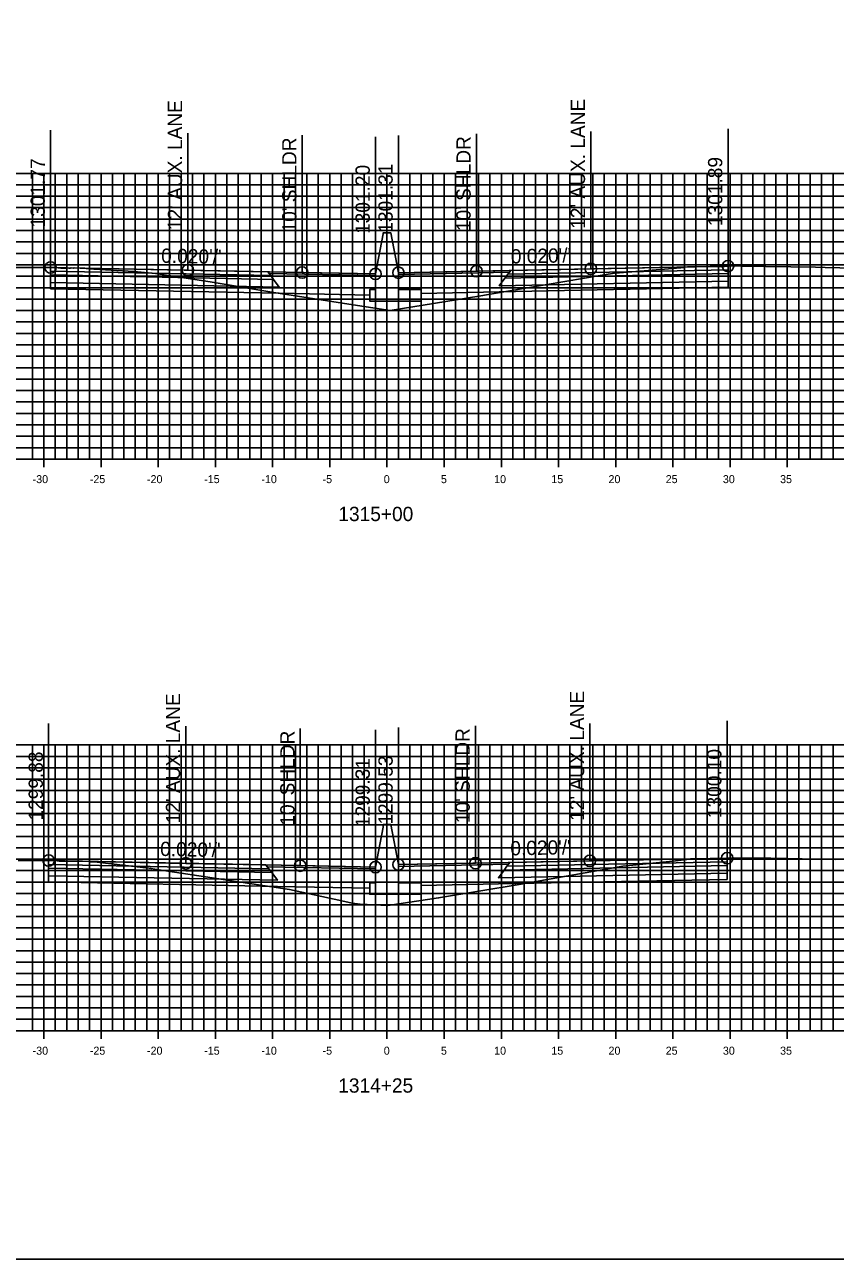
# Model space of a CAD drawing. Extents: x 674939 to 678919, y 750652 to 765176.
# Drawn here: x 678706.9 to 678777.7, y 750922.6 to 751030.6 of the extents above; entities that cross this region are included whole.
import ezdxf

# ---------------------------------------------------------------- set-up
doc = ezdxf.new("R2010")
doc.units = 0
for name, color, linetype in [('R_Alt Surface', 7, 'Continuous'), ('R_Axis', 7, 'Continuous'), ('R_Axis Annot', 7, 'Continuous'), ('R_Exist Surface', 7, 'Continuous'), ('R_Fin Surface', 7, 'Continuous'), ('R_Grid', 7, 'Continuous'), ('R_No Plot', 7, 'Continuous'), ('R_Proposed Road', 7, 'Continuous'), ('R_Xsect Elev', 7, 'Continuous'), ('R_Xsect Slope', 7, 'Continuous')]:
    doc.layers.add(name, color=color, linetype=linetype)

msp = doc.modelspace()

# ---------------------------------------------------------------- linework, layer by layer
at = {"layer": 'R_Alt Surface'}
for points in [[(678709.12, 751008.99), (678709.12, 751008.66), (678728.62, 751008.27), (678728.37, 751008.61)], [(678709.12, 751008.66), (678709.12, 751008), (678729.12, 751007.6), (678728.62, 751008.27)], [(678768.35, 751008.78), (678768.35, 751008.12), (678748.35, 751007.72), (678748.85, 751008.39)], [(678768.35, 751009.11), (678768.35, 751008.78), (678748.85, 751008.39), (678749.1, 751008.72)], [(678708.95, 750957.1), (678708.95, 750956.77), (678728.45, 750956.38), (678728.2, 750956.72)], [(678768.27, 750956.99), (678768.27, 750956.33), (678748.27, 750955.93), (678748.77, 750956.6)], [(678768.27, 750957.32), (678768.27, 750956.99), (678748.77, 750956.6), (678749.02, 750956.94)], [(678708.95, 750956.77), (678708.95, 750956.11), (678728.95, 750955.71), (678728.45, 750956.38)]]:
    msp.add_lwpolyline(points, close=True, dxfattribs=at)
for points in [[(678709.12, 751008), (678709.12, 751007.46), (678729.12, 751007.06), (678737.03, 751006.9)], [(678768.35, 751008.12), (678768.35, 751007.58), (678748.35, 751007.18), (678741.53, 751007.04)], [(678708.95, 750956.11), (678708.95, 750955.57), (678728.95, 750955.17), (678737.03, 750955.01)], [(678768.27, 750956.33), (678768.27, 750955.79), (678748.27, 750955.39), (678741.53, 750955.26)]]:
    msp.add_lwpolyline(points, dxfattribs=at)
at = {"layer": 'R_Axis'}
for p, q in [((678638.53, 750992.55), (678838.53, 750992.55)), ((678708.53, 750991.85), (678708.53, 750993.25)), ((678713.53, 750991.85), (678713.53, 750993.25)), ((678718.53, 750991.85), (678718.53, 750993.25)), ((678723.53, 750991.85), (678723.53, 750993.25)), ((678728.53, 750991.85), (678728.53, 750993.25)), ((678733.53, 750991.85), (678733.53, 750993.25)), ((678738.53, 750991.85), (678738.53, 750993.25)), ((678743.53, 750991.85), (678743.53, 750993.25)), ((678748.53, 750991.85), (678748.53, 750993.25)), ((678753.53, 750991.85), (678753.53, 750993.25)), ((678758.53, 750991.85), (678758.53, 750993.25)), ((678763.53, 750991.85), (678763.53, 750993.25)), ((678768.53, 750991.85), (678768.53, 750993.25)), ((678773.53, 750991.85), (678773.53, 750993.25)), ((678708.53, 750941.85), (678708.53, 750943.25)), ((678713.53, 750941.85), (678713.53, 750943.25)), ((678718.53, 750941.85), (678718.53, 750943.25)), ((678723.53, 750941.85), (678723.53, 750943.25)), ((678728.53, 750941.85), (678728.53, 750943.25)), ((678733.53, 750941.85), (678733.53, 750943.25)), ((678738.53, 750941.85), (678738.53, 750943.25)), ((678743.53, 750941.85), (678743.53, 750943.25)), ((678748.53, 750941.85), (678748.53, 750943.25)), ((678753.53, 750941.85), (678753.53, 750943.25)), ((678758.53, 750941.85), (678758.53, 750943.25)), ((678763.53, 750941.85), (678763.53, 750943.25)), ((678768.53, 750941.85), (678768.53, 750943.25)), ((678773.53, 750941.85), (678773.53, 750943.25)), ((678638.53, 750942.55), (678838.53, 750942.55))]:
    msp.add_line(p, q, dxfattribs=at)
at = {"layer": 'R_Exist Surface'}
for points in [[(678705.21, 751009.31), (678707.58, 751009.31), (678709.09, 751009.32), (678709.12, 751009.32), (678709.18, 751009.32), (678709.53, 751009.3), (678710.01, 751009.27), (678710.47, 751009.27), (678710.55, 751009.28), (678710.72, 751009.26), (678710.84, 751009.27), (678710.92, 751009.28), (678711.09, 751009.27), (678711.17, 751009.28), (678712.22, 751009.23), (678712.47, 751009.21), (678712.64, 751009.2), (678712.75, 751009.21), (678712.87, 751009.19), (678712.93, 751009.18), (678716.41, 751008.95), (678718.29, 751008.79), (678723.07, 751008.05), (678728.65, 751007.14), (678736.34, 751005.94), (678738.82, 751005.55), (678746.55, 751006.81), (678748.93, 751007.22), (678757.52, 751008.66), (678758.43, 751008.81), (678758.69, 751008.85), (678758.87, 751008.86), (678764.57, 751009.32), (678764.61, 751009.33), (678764.82, 751009.37), (678765.08, 751009.38), (678766.79, 751009.41), (678766.99, 751009.41), (678768.02, 751009.41), (678768.07, 751009.42), (678768.35, 751009.44), (678768.37, 751009.44), (678768.59, 751009.46), (678769.49, 751009.44), (678775.99, 751009.34), (678776.83, 751009.32), (678785.72, 751009.1)], [(678706.28, 750957.43), (678708.11, 750957.43), (678708.95, 750957.43), (678708.97, 750957.43), (678709.23, 750957.43), (678709.69, 750957.41), (678709.86, 750957.39), (678710.36, 750957.39), (678711.41, 750957.39), (678711.91, 750957.39), (678712.49, 750957.34), (678712.57, 750957.32), (678712.78, 750957.32), (678712.93, 750957.33), (678717.46, 750956.79), (678717.75, 750956.76), (678718.42, 750956.65), (678730, 750954.91), (678734.58, 750953.92), (678735.5, 750953.7), (678736.19, 750953.63), (678738.61, 750953.49), (678743.05, 750954.17), (678750.08, 750955.35), (678753.89, 750956.02), (678759.14, 750956.94), (678763.51, 750957.39), (678764.72, 750957.52), (678764.72, 750957.52), (678764.75, 750957.53), (678765.06, 750957.57), (678765.32, 750957.59), (678767.21, 750957.62), (678767.38, 750957.61), (678768.06, 750957.61), (678768.12, 750957.62), (678768.27, 750957.65), (678768.29, 750957.66), (678768.29, 750957.66), (678771.2, 750957.64), (678772.1, 750957.63), (678776.2, 750957.55), (678777.77, 750957.52)]]:
    msp.add_lwpolyline(points, dxfattribs=at)
at = {"layer": 'R_Fin Surface'}
for points in [[(678737.53, 751008.75), (678731.12, 751008.88), (678721.12, 751009.08), (678709.12, 751009.32)], [(678768.35, 751009.44), (678756.35, 751009.2), (678746.35, 751009), (678739.53, 751008.86)], [(678737.53, 750956.86), (678730.95, 750956.99), (678720.95, 750957.19), (678708.95, 750957.43)], [(678768.27, 750957.65), (678756.27, 750957.41), (678746.27, 750957.21), (678739.53, 750957.08)]]:
    msp.add_lwpolyline(points, dxfattribs=at)
for points in [[(678709.12, 751009.32), (678709.12, 751008.99), (678728.37, 751008.61), (678728.12, 751008.94)], [(678728.12, 751008.94), (678737.53, 751008.75), (678737.54, 751008.6), (678728.24, 751008.78)], [(678749.24, 751008.9), (678739.53, 751008.71), (678739.53, 751008.86), (678749.35, 751009.06)], [(678768.35, 751009.44), (678768.35, 751009.11), (678749.1, 751008.72), (678749.35, 751009.06)], [(678708.95, 750957.43), (678708.95, 750957.1), (678728.2, 750956.72), (678727.95, 750957.05)], [(678727.95, 750957.05), (678737.53, 750956.86), (678737.54, 750956.7), (678728.07, 750956.89)], [(678749.15, 750957.12), (678739.53, 750956.92), (678739.53, 750957.08), (678749.27, 750957.27)], [(678768.27, 750957.65), (678768.27, 750957.32), (678749.02, 750956.94), (678749.27, 750957.27)]]:
    msp.add_lwpolyline(points, close=True, dxfattribs=at)
at = {"layer": 'R_Grid'}
for p, q in [((678638.53, 751017.55), (678838.53, 751017.55)), ((678707.53, 750992.55), (678707.53, 751017.55)), ((678708.53, 750992.55), (678708.53, 751017.55)), ((678709.53, 750992.55), (678709.53, 751017.55)), ((678710.53, 750992.55), (678710.53, 751017.55)), ((678711.53, 750992.55), (678711.53, 751017.55)), ((678712.53, 750992.55), (678712.53, 751017.55)), ((678713.53, 750992.55), (678713.53, 751017.55)), ((678714.53, 750992.55), (678714.53, 751017.55)), ((678715.53, 750992.55), (678715.53, 751017.55)), ((678716.53, 750992.55), (678716.53, 751017.55)), ((678717.53, 750992.55), (678717.53, 751017.55)), ((678718.53, 750992.55), (678718.53, 751017.55)), ((678719.53, 750992.55), (678719.53, 751017.55)), ((678720.53, 750992.55), (678720.53, 751017.55)), ((678721.53, 750992.55), (678721.53, 751017.55)), ((678722.53, 750992.55), (678722.53, 751017.55)), ((678723.53, 750992.55), (678723.53, 751017.55)), ((678724.53, 750992.55), (678724.53, 751017.55)), ((678725.53, 750992.55), (678725.53, 751017.55)), ((678726.53, 750992.55), (678726.53, 751017.55)), ((678727.53, 750992.55), (678727.53, 751017.55)), ((678728.53, 750992.55), (678728.53, 751017.55)), ((678729.53, 750992.55), (678729.53, 751017.55)), ((678730.53, 750992.55), (678730.53, 751017.55)), ((678731.53, 750992.55), (678731.53, 751017.55)), ((678732.53, 750992.55), (678732.53, 751017.55)), ((678733.53, 750992.55), (678733.53, 751017.55)), ((678734.53, 750992.55), (678734.53, 751017.55)), ((678735.53, 750992.55), (678735.53, 751017.55)), ((678736.53, 750992.55), (678736.53, 751017.55)), ((678737.53, 750992.55), (678737.53, 751017.55)), ((678738.53, 750992.55), (678738.53, 751017.55)), ((678739.53, 750992.55), (678739.53, 751017.55)), ((678740.53, 750992.55), (678740.53, 751017.55)), ((678741.53, 750992.55), (678741.53, 751017.55)), ((678742.53, 750992.55), (678742.53, 751017.55)), ((678743.53, 750992.55), (678743.53, 751017.55)), ((678744.53, 750992.55), (678744.53, 751017.55)), ((678745.53, 750992.55), (678745.53, 751017.55)), ((678746.53, 750992.55), (678746.53, 751017.55)), ((678747.53, 750992.55), (678747.53, 751017.55)), ((678748.53, 750992.55), (678748.53, 751017.55)), ((678749.53, 750992.55), (678749.53, 751017.55)), ((678750.53, 750992.55), (678750.53, 751017.55)), ((678751.53, 750992.55), (678751.53, 751017.55)), ((678752.53, 750992.55), (678752.53, 751017.55)), ((678753.53, 750992.55), (678753.53, 751017.55)), ((678754.53, 750992.55), (678754.53, 751017.55)), ((678755.53, 750992.55), (678755.53, 751017.55)), ((678756.53, 750992.55), (678756.53, 751017.55)), ((678757.53, 750992.55), (678757.53, 751017.55)), ((678758.53, 750992.55), (678758.53, 751017.55)), ((678759.53, 750992.55), (678759.53, 751017.55)), ((678760.53, 750992.55), (678760.53, 751017.55)), ((678761.53, 750992.55), (678761.53, 751017.55)), ((678762.53, 750992.55), (678762.53, 751017.55)), ((678763.53, 750992.55), (678763.53, 751017.55)), ((678764.53, 750992.55), (678764.53, 751017.55)), ((678765.53, 750992.55), (678765.53, 751017.55)), ((678766.53, 750992.55), (678766.53, 751017.55)), ((678767.53, 750992.55), (678767.53, 751017.55)), ((678768.53, 750992.55), (678768.53, 751017.55)), ((678769.53, 750992.55), (678769.53, 751017.55)), ((678770.53, 750992.55), (678770.53, 751017.55)), ((678771.53, 750992.55), (678771.53, 751017.55)), ((678772.53, 750992.55), (678772.53, 751017.55)), ((678773.53, 750992.55), (678773.53, 751017.55)), ((678774.53, 750992.55), (678774.53, 751017.55)), ((678775.53, 750992.55), (678775.53, 751017.55)), ((678776.53, 750992.55), (678776.53, 751017.55)), ((678777.53, 750992.55), (678777.53, 751017.55)), ((678638.53, 751016.55), (678838.53, 751016.55)), ((678638.53, 751015.55), (678838.53, 751015.55)), ((678638.53, 751014.55), (678838.53, 751014.55)), ((678638.53, 751013.55), (678838.53, 751013.55)), ((678638.53, 751012.55), (678838.53, 751012.55)), ((678638.53, 751011.55), (678838.53, 751011.55)), ((678638.53, 751010.55), (678838.53, 751010.55)), ((678638.53, 751009.55), (678838.53, 751009.55)), ((678638.53, 751008.55), (678838.53, 751008.55)), ((678638.53, 751007.55), (678838.53, 751007.55)), ((678638.53, 751006.55), (678838.53, 751006.55)), ((678638.53, 751005.55), (678838.53, 751005.55)), ((678638.53, 751004.55), (678838.53, 751004.55)), ((678638.53, 751003.55), (678838.53, 751003.55)), ((678638.53, 751002.55), (678838.53, 751002.55)), ((678638.53, 751001.55), (678838.53, 751001.55)), ((678638.53, 751000.55), (678838.53, 751000.55)), ((678638.53, 750999.55), (678838.53, 750999.55)), ((678638.53, 750998.55), (678838.53, 750998.55)), ((678638.53, 750997.55), (678838.53, 750997.55)), ((678638.53, 750996.55), (678838.53, 750996.55)), ((678638.53, 750995.55), (678838.53, 750995.55)), ((678638.53, 750994.55), (678838.53, 750994.55)), ((678638.53, 750993.55), (678838.53, 750993.55)), ((678638.53, 750992.55), (678838.53, 750992.55)), ((678638.53, 750967.55), (678838.53, 750967.55)), ((678638.53, 750966.55), (678838.53, 750966.55)), ((678707.53, 750942.55), (678707.53, 750967.55)), ((678708.53, 750942.55), (678708.53, 750967.55)), ((678709.53, 750942.55), (678709.53, 750967.55)), ((678710.53, 750942.55), (678710.53, 750967.55)), ((678711.53, 750942.55), (678711.53, 750967.55)), ((678712.53, 750942.55), (678712.53, 750967.55)), ((678713.53, 750942.55), (678713.53, 750967.55)), ((678714.53, 750942.55), (678714.53, 750967.55)), ((678715.53, 750942.55), (678715.53, 750967.55)), ((678716.53, 750942.55), (678716.53, 750967.55)), ((678717.53, 750942.55), (678717.53, 750967.55)), ((678718.53, 750942.55), (678718.53, 750967.55)), ((678719.53, 750942.55), (678719.53, 750967.55)), ((678720.53, 750942.55), (678720.53, 750967.55)), ((678721.53, 750942.55), (678721.53, 750967.55)), ((678722.53, 750942.55), (678722.53, 750967.55)), ((678723.53, 750942.55), (678723.53, 750967.55)), ((678724.53, 750942.55), (678724.53, 750967.55)), ((678725.53, 750942.55), (678725.53, 750967.55)), ((678726.53, 750942.55), (678726.53, 750967.55)), ((678727.53, 750942.55), (678727.53, 750967.55)), ((678728.53, 750942.55), (678728.53, 750967.55)), ((678729.53, 750942.55), (678729.53, 750967.55)), ((678730.53, 750942.55), (678730.53, 750967.55)), ((678731.53, 750942.55), (678731.53, 750967.55)), ((678732.53, 750942.55), (678732.53, 750967.55)), ((678733.53, 750942.55), (678733.53, 750967.55)), ((678734.53, 750942.55), (678734.53, 750967.55)), ((678735.53, 750942.55), (678735.53, 750967.55)), ((678736.53, 750942.55), (678736.53, 750967.55)), ((678737.53, 750942.55), (678737.53, 750967.55)), ((678738.53, 750942.55), (678738.53, 750967.55)), ((678739.53, 750942.55), (678739.53, 750967.55)), ((678740.53, 750942.55), (678740.53, 750967.55)), ((678741.53, 750942.55), (678741.53, 750967.55)), ((678742.53, 750942.55), (678742.53, 750967.55)), ((678743.53, 750942.55), (678743.53, 750967.55)), ((678744.53, 750942.55), (678744.53, 750967.55)), ((678745.53, 750942.55), (678745.53, 750967.55)), ((678746.53, 750942.55), (678746.53, 750967.55)), ((678747.53, 750942.55), (678747.53, 750967.55)), ((678748.53, 750942.55), (678748.53, 750967.55)), ((678749.53, 750942.55), (678749.53, 750967.55)), ((678750.53, 750942.55), (678750.53, 750967.55)), ((678751.53, 750942.55), (678751.53, 750967.55)), ((678752.53, 750942.55), (678752.53, 750967.55)), ((678753.53, 750942.55), (678753.53, 750967.55)), ((678754.53, 750942.55), (678754.53, 750967.55)), ((678755.53, 750942.55), (678755.53, 750967.55)), ((678756.53, 750942.55), (678756.53, 750967.55)), ((678757.53, 750942.55), (678757.53, 750967.55)), ((678758.53, 750942.55), (678758.53, 750967.55)), ((678759.53, 750942.55), (678759.53, 750967.55)), ((678760.53, 750942.55), (678760.53, 750967.55)), ((678761.53, 750942.55), (678761.53, 750967.55)), ((678762.53, 750942.55), (678762.53, 750967.55)), ((678763.53, 750942.55), (678763.53, 750967.55)), ((678764.53, 750942.55), (678764.53, 750967.55)), ((678765.53, 750942.55), (678765.53, 750967.55)), ((678766.53, 750942.55), (678766.53, 750967.55)), ((678767.53, 750942.55), (678767.53, 750967.55)), ((678768.53, 750942.55), (678768.53, 750967.55)), ((678769.53, 750942.55), (678769.53, 750967.55)), ((678770.53, 750942.55), (678770.53, 750967.55)), ((678771.53, 750942.55), (678771.53, 750967.55)), ((678772.53, 750942.55), (678772.53, 750967.55)), ((678773.53, 750942.55), (678773.53, 750967.55)), ((678774.53, 750942.55), (678774.53, 750967.55)), ((678775.53, 750942.55), (678775.53, 750967.55)), ((678776.53, 750942.55), (678776.53, 750967.55)), ((678777.53, 750942.55), (678777.53, 750967.55)), ((678638.53, 750965.55), (678838.53, 750965.55)), ((678638.53, 750964.55), (678838.53, 750964.55)), ((678638.53, 750963.55), (678838.53, 750963.55)), ((678638.53, 750962.55), (678838.53, 750962.55)), ((678638.53, 750961.55), (678838.53, 750961.55)), ((678638.53, 750960.55), (678838.53, 750960.55)), ((678638.53, 750959.55), (678838.53, 750959.55)), ((678638.53, 750958.55), (678838.53, 750958.55)), ((678638.53, 750957.55), (678838.53, 750957.55)), ((678638.53, 750956.55), (678838.53, 750956.55)), ((678638.53, 750955.55), (678838.53, 750955.55)), ((678638.53, 750954.55), (678838.53, 750954.55)), ((678638.53, 750953.55), (678838.53, 750953.55)), ((678638.53, 750952.55), (678838.53, 750952.55)), ((678638.53, 750951.55), (678838.53, 750951.55)), ((678638.53, 750950.55), (678838.53, 750950.55)), ((678638.53, 750949.55), (678838.53, 750949.55)), ((678638.53, 750948.55), (678838.53, 750948.55)), ((678638.53, 750947.55), (678838.53, 750947.55)), ((678638.53, 750946.55), (678838.53, 750946.55)), ((678638.53, 750945.55), (678838.53, 750945.55)), ((678638.53, 750944.55), (678838.53, 750944.55)), ((678638.53, 750943.55), (678838.53, 750943.55)), ((678638.53, 750942.55), (678838.53, 750942.55))]:
    msp.add_line(p, q, dxfattribs=at)
at = {"layer": 'R_No Plot'}
msp.add_lwpolyline([(678578.53, 750922.55), (678918.53, 750922.55), (678918.53, 751142.55), (678578.53, 751142.55)], close=True, dxfattribs=at)
for centre in [(678709.12, 751009.32), (678768.35, 751009.44), (678721.12, 751009.08), (678731.12, 751008.88), (678737.53, 751008.75), (678739.53, 751008.86), (678746.35, 751009), (678756.35, 751009.2), (678708.95, 750957.43), (678756.27, 750957.41), (678768.27, 750957.65), (678720.95, 750957.19), (678730.95, 750956.99), (678737.53, 750956.86), (678739.53, 750957.08), (678746.27, 750957.21)]:
    msp.add_circle(centre, 0.5, dxfattribs=at)
at = {"layer": 'R_Proposed Road'}
for points in [[(678738.2, 751012.25), (678737.53, 751008.75)], [(678738.86, 751012.36), (678738.86, 751012.36), (678738.2, 751012.36), (678738.2, 751012.25)], [(678738.86, 751012.36), (678739.53, 751008.86)], [(678737.53, 751008.75), (678737.53, 751007.38), (678737.03, 751007.38), (678737.03, 751006.38), (678741.53, 751006.38), (678741.53, 751007.38), (678739.53, 751007.38), (678739.53, 751008.86)], [(678738.2, 750960.36), (678737.53, 750956.86)], [(678738.86, 750960.58), (678738.86, 750960.58), (678738.2, 750960.58), (678738.2, 750960.36)], [(678738.86, 750960.58), (678739.53, 750957.08)], [(678737.53, 750956.86), (678737.53, 750955.48), (678737.03, 750955.48), (678737.03, 750954.48), (678741.53, 750954.48), (678741.53, 750955.48), (678739.53, 750955.48), (678739.53, 750957.08)]]:
    msp.add_lwpolyline(points, dxfattribs=at)
at = {"layer": 'R_Xsect Elev'}
for p, q in [((678709.12, 751009.32), (678709.12, 751021.32)), ((678721.12, 751009.08), (678721.12, 751021.08)), ((678731.12, 751008.88), (678731.12, 751020.88)), ((678737.53, 751008.75), (678737.53, 751020.75)), ((678739.53, 751008.86), (678739.53, 751020.86)), ((678746.35, 751009), (678746.35, 751021)), ((678756.35, 751009.2), (678756.35, 751021.2)), ((678768.35, 751009.44), (678768.35, 751021.44)), ((678708.95, 750957.43), (678708.95, 750969.43)), ((678720.95, 750957.19), (678720.95, 750969.19)), ((678730.95, 750956.99), (678730.95, 750968.99)), ((678737.53, 750956.86), (678737.53, 750968.86)), ((678739.53, 750957.08), (678739.53, 750969.08)), ((678746.27, 750957.21), (678746.27, 750969.21)), ((678756.27, 750957.41), (678756.27, 750969.41)), ((678768.27, 750957.65), (678768.27, 750969.65))]:
    msp.add_line(p, q, dxfattribs=at)

# ---------------------------------------------------------------- texts
at = {"layer": 'R_Axis Annot'}
for s, height, p in [('-30', 0.7, (678707.55, 750990.45)), ('-25', 0.7, (678712.55, 750990.45)), ('-20', 0.7, (678717.55, 750990.45)), ('-15', 0.7, (678722.55, 750990.45)), ('-10', 0.7, (678727.55, 750990.45)), ('-5', 0.7, (678732.9, 750990.45)), ('0', 0.7, (678738.25, 750990.45)), ('5', 0.7, (678743.25, 750990.45)), ('10', 0.7, (678747.9, 750990.45)), ('15', 0.7, (678752.9, 750990.45)), ('20', 0.7, (678757.9, 750990.45)), ('25', 0.7, (678762.9, 750990.45)), ('30', 0.7, (678767.9, 750990.45)), ('35', 0.7, (678772.9, 750990.45)), ('1315+00', 1.25, (678734.28, 750987.13)), ('-30', 0.7, (678707.55, 750940.45)), ('-25', 0.7, (678712.55, 750940.45)), ('-20', 0.7, (678717.55, 750940.45)), ('-15', 0.7, (678722.55, 750940.45)), ('-10', 0.7, (678727.55, 750940.45)), ('-5', 0.7, (678732.9, 750940.45)), ('0', 0.7, (678738.25, 750940.45)), ('5', 0.7, (678743.25, 750940.45)), ('10', 0.7, (678747.9, 750940.45)), ('15', 0.7, (678752.9, 750940.45)), ('20', 0.7, (678757.9, 750940.45)), ('25', 0.7, (678762.9, 750940.45)), ('30', 0.7, (678767.9, 750940.45)), ('35', 0.7, (678772.9, 750940.45)), ('1314+25', 1.25, (678734.27, 750937.13))]:
    msp.add_text(s, height=height, dxfattribs=at).set_placement(p)
at = {"layer": 'R_Xsect Elev'}
for s, p in [("12' AUX. LANE", (678720.62, 751012.58)), ("12' AUX. LANE", (678755.85, 751012.7)), ("10' SHLDR", (678730.62, 751012.38)), ("10' SHLDR", (678745.85, 751012.5)), ('1301.77', (678708.62, 751012.82)), ('1301.89', (678767.85, 751012.94)), ('1301.20', (678737.03, 751012.25)), ('1301.31', (678739.03, 751012.36)), ("12' AUX. LANE", (678720.45, 750960.69)), ("12' AUX. LANE", (678755.77, 750960.91)), ("10' SHLDR", (678730.45, 750960.49)), ("10' SHLDR", (678745.77, 750960.71)), ('1299.88', (678708.45, 750960.93)), ('1299.53', (678739.03, 750960.58)), ('1300.10', (678767.77, 750961.15)), ('1299.31', (678737.03, 750960.36))]:
    msp.add_text(s, height=1.25, rotation=90, dxfattribs=at).set_placement(p)
at = {"layer": 'R_Xsect Slope'}
for rotation, p in [(358.8542, (678718.78, 751009.73)), (1.1458, (678749.37, 751009.66)), (358.8542, (678718.69, 750957.84)), (1.1458, (678749.33, 750957.88))]:
    msp.add_text("0.020'/'", height=1.25, rotation=rotation, dxfattribs=at).set_placement(p)

doc.saveas('drawing.dxf')
